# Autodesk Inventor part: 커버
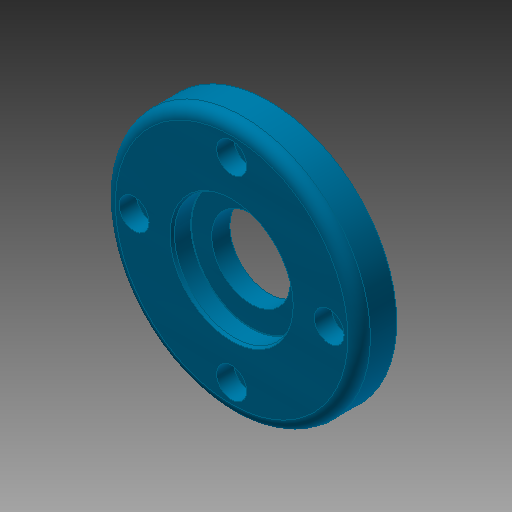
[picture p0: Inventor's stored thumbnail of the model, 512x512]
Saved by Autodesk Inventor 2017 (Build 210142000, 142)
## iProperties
Created: 2016-06
Part Number: 커버
Material: 알루미늄 6061
Document SubType Name: Modeling
Designer: mduedu
Density: 2.71 g/cm^3
Appearance: 하늘색 중간
Author: mduedu
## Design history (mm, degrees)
sketch "스케치1"
  geometry: C1 r 34 at (0, 0); 1 further point
  constraints: 1 centre point, 1 coincident
  dimensions: "d0" = 68 diameter of C1
extrude "돌출1" new body sketch "스케치1" distance "d2" = 10; taper "d3" = 0 deg
sketch "스케치2"
  geometry: C1 r 21 at (0, 0); 1 further point
  constraints: 1 centre point, 1 coincident
  dimensions: "d4" = 42 diameter of C1
extrude "돌출2" join sketch "스케치2" distance "d6" = 3; taper "d7" = 0 deg
fillet "모깎기1" dims "d8" = 3
hole "구멍1" diameter "d11" = 35; stored, may be unused: countersink angle "d15" = 90 deg, drill point angle "d17" = 0 deg; dims "d9" = 10, "d10" = 10, "d12" = 6, "d13" = 4, "d14" = 2, "d16" = 3
hole "구멍2" diameter "d20" = 32; stored, may be unused: countersink angle "d24" = 90 deg, drill point angle "d26" = 0 deg; dims "d21" = 6, "d22" = 4, "d23" = 2, "d25" = 5.2, "d46" = 10, "d47" = 10
hole "구멍3" diameter "d29" = 21; stored, may be unused: countersink angle "d33" = 90 deg, drill point angle "d35" = 0 deg; dims "d27" = 10, "d28" = 10, "d30" = 6, "d31" = 4, "d32" = 2, "d34" = 5
fillet "모깎기2" dims "d36" = 3
fillet "모깎기3" dims "d37" = 0.1
chamfer "모따기1" distance "d38" = 0.75; stored, may be unused: second distance "d39" = 2, angle "d40" = 30 deg
chamfer "모따기2" distance "d42" = 0.5; stored, may be unused: second distance "d43" = 2, angle "d44" = 30 deg
sketch "스케치3" dims "d48" = 52
  geometry: 6 further points
  constraints: 2 vertical alignment, 1 coincident, 7 other
  dimensions: "d51" = 360 deg dimension on point (0, 0) point (0, 26) (derived)
sketch "스케치4"
  geometry: 4 further points
hole "구멍4" sketch "스케치4" at (0, 26), (-26, 0), (0, -26), (26, 0) diameter "d53" = 4.5; stored, may be unused: countersink angle "d57" = 90 deg, drill point angle "d59" = 0 deg; dims "d54" = 6, "d55" = 8, "d56" = 4.6, "d58" = 8
node "솔리드1"
